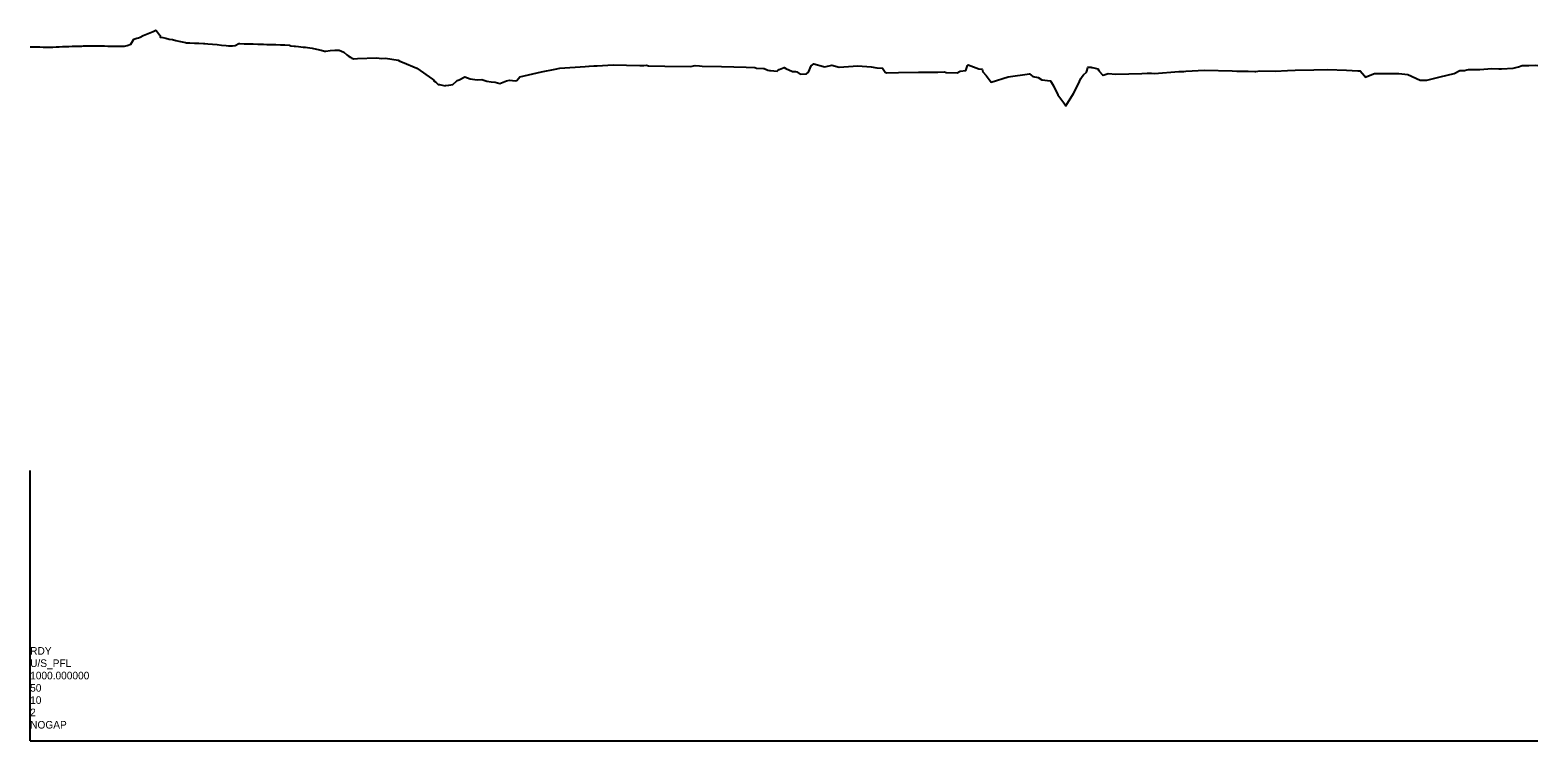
# Model space of a CAD drawing. Extents: x 1726619 to 1729848, y 535683 to 539687.
# Drawn here: x 1726619 to 1728011, y 536856 to 537513 of the extents above; entities that cross this region are included whole.
import ezdxf

# ---------------------------------------------------------------- set-up
doc = ezdxf.new("R2010")
doc.units = 0
doc.layers.add('Exist Profile Cell', color=7, linetype='Continuous')
doc.layers.add('Prop Grid Mask', color=7, linetype='Continuous')

msp = doc.modelspace()

# ---------------------------------------------------------------- linework, layer by layer
at = {"layer": 'Exist Profile Cell'}
for q in [(1726618.5, 537106.3), (1728010.7, 536856.3), (1726618.5, 536856.3)]:
    msp.add_line((1726618.5, 536856.3), q, dxfattribs=at)
at = {"layer": 'Prop Grid Mask'}
msp.add_lwpolyline([(1726618.5, 537497.8), (1726620.3, 537497.8), (1726621.5, 537497.7), (1726624.5, 537497.6), (1726627.5, 537497.6), (1726630.4, 537497.5), (1726633.4, 537497.4), (1726636.4, 537497.3), (1726639.4, 537497.5), (1726642.4, 537497.6), (1726645.4, 537497.7), (1726648.4, 537497.9), (1726651.4, 537498), (1726654.3, 537498.1), (1726657.3, 537498.2), (1726659.5, 537498.3), (1726660.3, 537498.4), (1726663.3, 537498.4), (1726666.3, 537498.4), (1726667.8, 537498.5), (1726669.3, 537498.5), (1726672.3, 537498.5), (1726675.2, 537498.5), (1726678.2, 537498.5), (1726681.2, 537498.6), (1726682.5, 537498.6), (1726684.2, 537498.6), (1726687.2, 537498.5), (1726690.2, 537498.4), (1726693.2, 537498.4), (1726696.1, 537498.3), (1726699.1, 537498.3), (1726702.1, 537498.2), (1726705.1, 537498.2), (1726705.7, 537498.2), (1726708.1, 537498.9), (1726711.5, 537500), (1726714.3, 537504.8), (1726717, 537505.6), (1726718.4, 537506), (1726720, 537506.7), (1726723, 537508), (1726726, 537509.3), (1726729, 537510.6), (1726732, 537512), (1726734.5, 537513.1), (1726735.3, 537512.5), (1726738, 537508.8), (1726738.5, 537508), (1726738.6, 537506.7), (1726740.9, 537506.2), (1726743.9, 537505.6), (1726746.9, 537504.9), (1726749.9, 537504.3), (1726752.9, 537503.6), (1726755.9, 537502.9), (1726758.9, 537502.3), (1726761.8, 537501.6), (1726763, 537501.3), (1726764.4, 537501.5), (1726766, 537501.4), (1726770.2, 537501.2), (1726774.4, 537501.1), (1726778.6, 537500.9), (1726779.8, 537500.8), (1726782.7, 537500.5), (1726786.9, 537500.1), (1726791.1, 537499.7), (1726795.3, 537499.3), (1726799.5, 537498.8), (1726801.6, 537498.6), (1726803.6, 537498.6), (1726805.2, 537498.6), (1726807.8, 537499), (1726811.3, 537500.7), (1726812, 537500.7), (1726816.2, 537500.5), (1726820.4, 537500.4), (1726824.5, 537500.3), (1726828.7, 537500.1), (1726832.9, 537500), (1726834, 537500), (1726837.1, 537499.9), (1726841.3, 537499.8), (1726845.4, 537499.7), (1726849.6, 537499.6), (1726853.8, 537499.5), (1726858, 537499.2), (1726859.2, 537498.6), (1726862.2, 537498.3), (1726863.5, 537498.2), (1726866.3, 537497.9), (1726870.5, 537497.5), (1726872.9, 537497.3), (1726874.7, 537497), (1726879, 537496.5), (1726883, 537495.5), (1726887.2, 537494.5), (1726890.3, 537493.8), (1726891.4, 537493.8), (1726895.6, 537494.2), (1726899.8, 537494.5), (1726903.4, 537494.7), (1726903.9, 537494.5), (1726908.3, 537492.8), (1726910.8, 537490.4), (1726912.3, 537489.4), (1726914.7, 537487.8), (1726915.6, 537487.3), (1726916.5, 537487), (1726917.2, 537486.7), (1726920.7, 537486.9), (1726938.2, 537487.5), (1726943.3, 537487), (1726946.7, 537487.3), (1726958.3, 537485.3), (1726959.8, 537484.4), (1726962.3, 537483.6), (1726975.6, 537478), (1726990, 537467.8), (1726991.1, 537467.3), (1726991.4, 537466.2), (1726992.7, 537465.4), (1726995.4, 537462.9), (1726996.4, 537462.8), (1727001.8, 537461.7), (1727002.1, 537461.8), (1727005.1, 537462.3), (1727008.8, 537462.9), (1727012.2, 537465.9), (1727012.8, 537466.6), (1727014.7, 537467.2), (1727020, 537470.1), (1727024.9, 537468), (1727031.2, 537467.2), (1727035.7, 537467.6), (1727040.2, 537465.9), (1727044.1, 537465.3), (1727047.9, 537465), (1727052.1, 537463.8), (1727058.4, 537466.4), (1727061.1, 537466.8), (1727066.6, 537466.3), (1727067.8, 537466.7), (1727070.8, 537470.1), (1727090.8, 537474.7), (1727103.4, 537477), (1727107.7, 537478), (1727131, 537479.4), (1727134.8, 537479.9), (1727139, 537480), (1727142, 537480.1), (1727156.9, 537480.9), (1727181.6, 537480.5), (1727185.2, 537480.5), (1727187.7, 537480.8), (1727189.6, 537480.1), (1727204.7, 537479.8), (1727228.2, 537479.6), (1727232.6, 537480.5), (1727236.5, 537480), (1727239.1, 537479.7), (1727257, 537479.6), (1727279.7, 537479), (1727287.8, 537478.7), (1727289.3, 537478), (1727295.8, 537477.8), (1727296.2, 537477.7), (1727299.8, 537476.2), (1727301.1, 537475.8), (1727302, 537475.7), (1727308.2, 537475.1), (1727309, 537475.8), (1727310.2, 537476.8), (1727314.9, 537478.7), (1727316.3, 537477.7), (1727322.3, 537475), (1727324.3, 537474.8), (1727325.3, 537475), (1727326.6, 537474.6), (1727329.4, 537472.4), (1727335.5, 537472.8), (1727337.2, 537474.4), (1727339.6, 537480.1), (1727342.2, 537482.1), (1727351, 537479.4), (1727352.3, 537479.1), (1727358.9, 537480.8), (1727365.4, 537478.9), (1727382.8, 537480.2), (1727395.1, 537479.1), (1727400.2, 537478.2), (1727405.5, 537478.1), (1727408.1, 537474.4), (1727409.1, 537473.6), (1727420.4, 537474.1), (1727438.9, 537474.2), (1727441.2, 537474.2), (1727456.7, 537474.2), (1727462.8, 537474.6), (1727464.4, 537474), (1727474.4, 537473.6), (1727477.2, 537475.1), (1727482.5, 537475.9), (1727484.1, 537480.5), (1727484.7, 537480.9), (1727494.5, 537477.5), (1727497.6, 537476.9), (1727498.1, 537474.7), (1727501.2, 537471.1), (1727505.8, 537465.1), (1727521.6, 537469.9), (1727541.2, 537472.7), (1727544.5, 537470.2), (1727549.4, 537469.4), (1727552.6, 537467.1), (1727560.6, 537466.3), (1727563.4, 537461.6), (1727567.4, 537453.3), (1727573, 537445.8), (1727574.9, 537443.2), (1727581.8, 537454.4), (1727586.3, 537462.9), (1727588.6, 537468.4), (1727589.8, 537470.2), (1727591.1, 537471.9), (1727593.8, 537474.3), (1727594.4, 537476.1), (1727595.1, 537478.9), (1727598.1, 537478.8), (1727598.8, 537478.7), (1727599.3, 537478.7), (1727600.7, 537478.4), (1727604.3, 537477.3), (1727605.2, 537475.7), (1727605.7, 537475.2), (1727608.8, 537471.9), (1727609.3, 537471.5), (1727613.1, 537472.8), (1727614, 537473), (1727620.9, 537472.5), (1727644.9, 537473.1), (1727649.9, 537473.2), (1727654, 537473.3), (1727656.7, 537473.1), (1727679.1, 537474.8), (1727680.2, 537474.9), (1727683.7, 537475), (1727685.8, 537475.1), (1727702.8, 537476), (1727728.3, 537475.5), (1727732.7, 537475.2), (1727743.2, 537475.3), (1727749.3, 537475), (1727750.2, 537475), (1727753.9, 537475.4), (1727768.1, 537475.2), (1727779.4, 537475.8), (1727786.5, 537476.1), (1727804, 537476.5), (1727816.6, 537476.8), (1727834.1, 537476), (1727844.5, 537475.6), (1727846.1, 537475.6), (1727846.5, 537475.4), (1727850.7, 537470.8), (1727851.4, 537469.8), (1727859.8, 537473.1), (1727882.4, 537473.1), (1727890.5, 537472.1), (1727902.1, 537467), (1727902.6, 537467), (1727908.3, 537467), (1727920.6, 537469.9), (1727933.5, 537472.9), (1727938.6, 537475.7), (1727943.1, 537475.9), (1727945.1, 537476.3), (1727946.7, 537476.6), (1727956.7, 537476.8), (1727957.1, 537476.8), (1727968.2, 537477.7), (1727974.7, 537477.5), (1727977.2, 537477.5), (1727988, 537478), (1727992.7, 537479.3), (1727996.2, 537480.3), (1728002.3, 537480.4), (1728008.6, 537480.7), (1728010.7, 537480.4)], dxfattribs=at)

# ---------------------------------------------------------------- texts
at = {"layer": 'Exist Profile Cell'}
for s, p in [('U/S_PFL', (1726618.5, 536924.6)), ('RDY', (1726618.5, 536936)), ('1000.000000', (1726618.5, 536913.2)), ('50', (1726618.5, 536901.8)), ('10', (1726618.5, 536890.5)), ('2', (1726618.5, 536879.1)), ('NOGAP', (1726618.5, 536867.7))]:
    msp.add_text(s, height=7, dxfattribs=at).set_placement(p)

doc.saveas('drawing.dxf')
